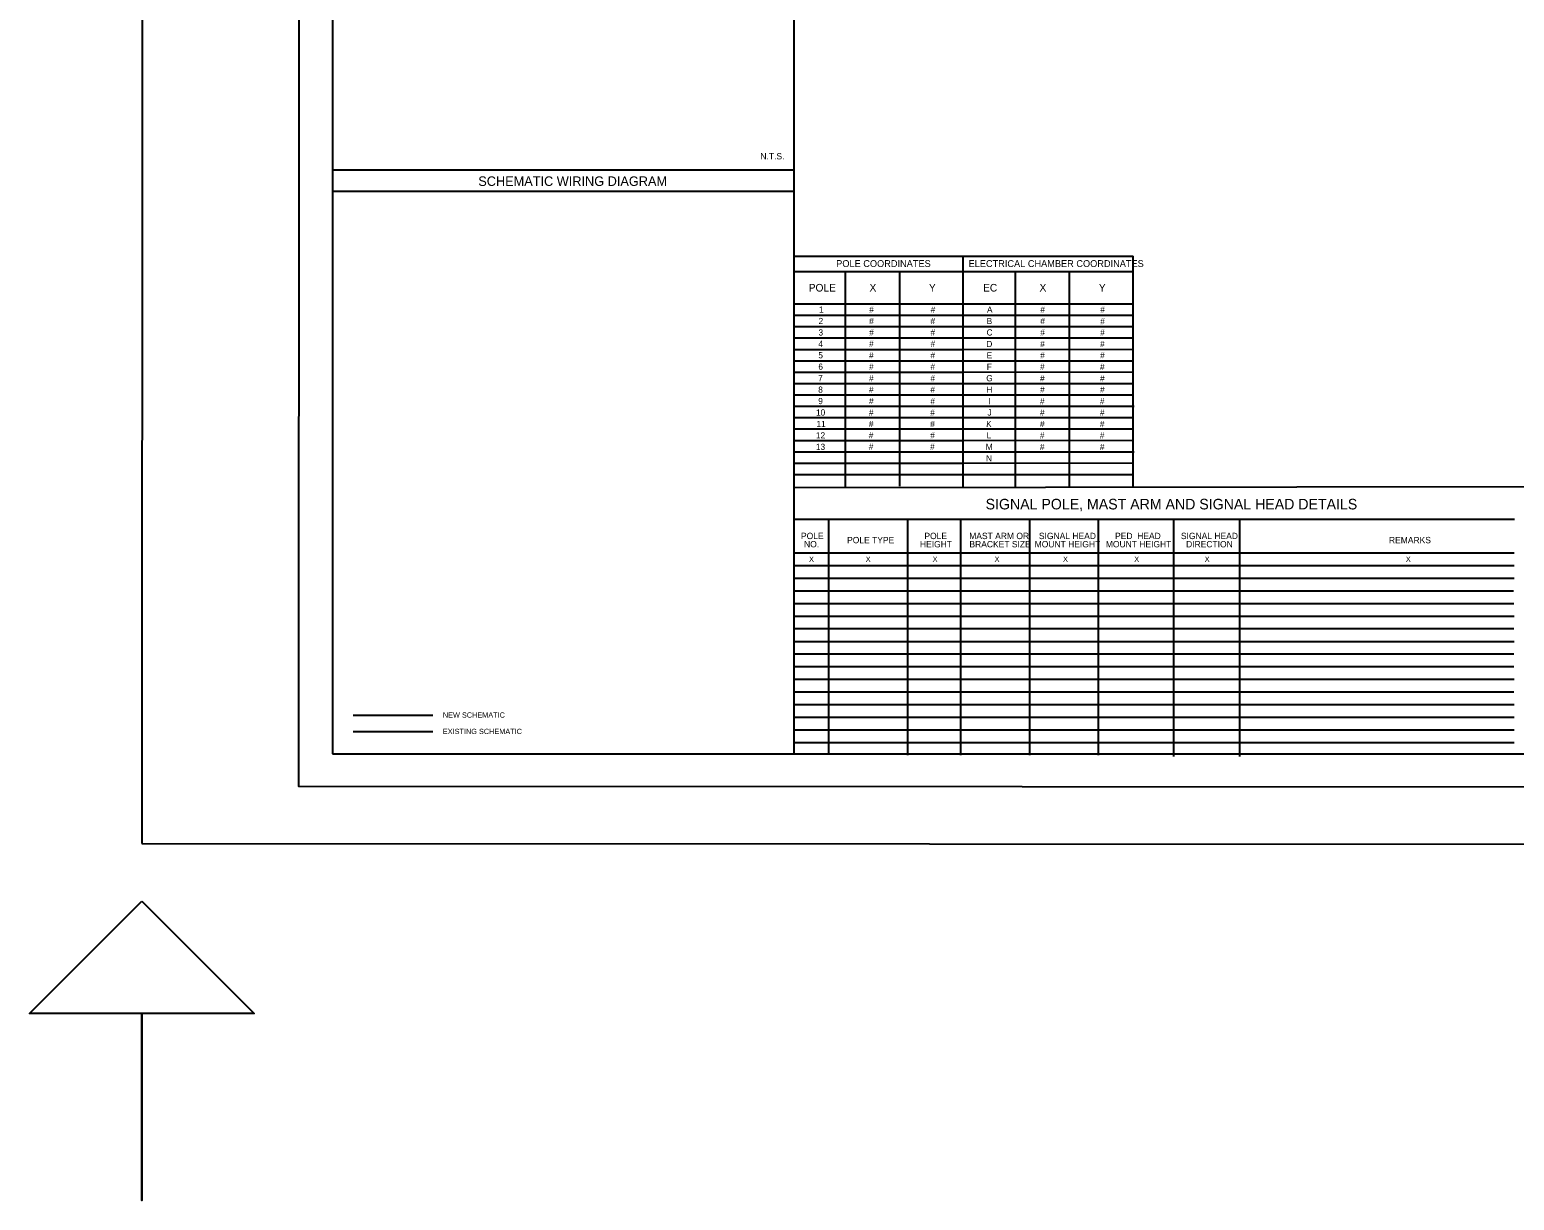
# Model space of a CAD drawing. Extents: x 595568 to 603392, y 4837996 to 4846579.
# Drawn here: x 603031.2 to 603171.6, y 4846357.1 to 4846467.9 of the extents above; entities that cross this region are included whole.
import ezdxf

# ---------------------------------------------------------------- set-up
doc = ezdxf.new("R2010")
doc.units = 0
for name, color, linetype in [('-PRINT FULLSIZE', 7, 'Continuous'), ('-PRINT HALFSIZE', 7, 'Continuous'), ('ENG_BORDER', 7, 'Continuous'), ('ENG_TITLEBLOCK', 7, 'Continuous'), ('ENG_TX_TITLEBLOCK', 7, 'Continuous'), ('ENG_WK_MISC-1', 7, 'Continuous'), ('TCS_TX_LEGEND', 7, 'Continuous'), ('TCS_WR_W', 7, 'Continuous'), ('TCS_WR_W-EXIST', 7, 'Continuous')]:
    doc.layers.add(name, color=color, linetype=linetype)

msp = doc.modelspace()

# ---------------------------------------------------------------- linework, layer by layer
at = {"layer": '-PRINT FULLSIZE'}
msp.add_lwpolyline([(603041.76, 4846390.89), (603265.21, 4846390.8), (603265.27, 4846543.39), (603041.82, 4846543.47)], close=True, dxfattribs=at)
at = {"layer": '-PRINT HALFSIZE'}
msp.add_lwpolyline([(603056.66, 4846536.38), (603261.88, 4846536.3), (603261.82, 4846396.2), (603056.6, 4846396.28)], close=True, dxfattribs=at)
at = {"layer": 'ENG_BORDER'}
msp.add_line((603103.46, 4846399.39), (603103.46, 4846533.88), dxfattribs=at)
for points in [[(603059.79, 4846533.88), (603059.79, 4846399.39)], [(603059.79, 4846399.39), (603258.62, 4846399.39), (603258.62, 4846533.88)]]:
    msp.add_lwpolyline(points, dxfattribs=at)
at = {"layer": 'ENG_TITLEBLOCK'}
for p, q in [((603059.79, 4846454.61), (603103.46, 4846454.61)), ((603059.79, 4846452.6), (603103.46, 4846452.6)), ((603103.46, 4846446.45), (603135.51, 4846446.45)), ((603119.44, 4846424.58), (603119.44, 4846446.45)), ((603135.5, 4846424.71), (603135.5, 4846446.45)), ((603103.46, 4846445.01), (603108.32, 4846445.01)), ((603108.32, 4846424.58), (603108.32, 4846445.01)), ((603108.32, 4846445.01), (603113.34, 4846445.01)), ((603113.34, 4846445.01), (603113.44, 4846445.01)), ((603113.44, 4846445.01), (603119.46, 4846445.01)), ((603113.44, 4846424.69), (603113.44, 4846444.98)), ((603119.43, 4846445.02), (603124.32, 4846445.02)), ((603124.32, 4846445.02), (603129.5, 4846445.02)), ((603124.39, 4846424.68), (603124.39, 4846445.01)), ((603129.5, 4846445.02), (603135.53, 4846445.01)), ((603129.5, 4846424.7), (603129.5, 4846445.01)), ((603103.46, 4846441.95), (603119.33, 4846441.95)), ((603119.33, 4846441.95), (603135.5, 4846441.95)), ((603103.46, 4846440.87), (603119.48, 4846440.87)), ((603103.46, 4846439.8), (603119.49, 4846439.79)), ((603119.48, 4846440.87), (603135.55, 4846440.88)), ((603119.49, 4846439.79), (603135.56, 4846439.8)), ((603103.46, 4846438.72), (603119.52, 4846438.72)), ((603119.52, 4846438.72), (603135.59, 4846438.73)), ((603103.46, 4846437.64), (603119.49, 4846437.64)), ((603119.49, 4846437.64), (603135.56, 4846437.65)), ((603103.46, 4846436.57), (603119.47, 4846436.57)), ((603103.46, 4846435.49), (603119.47, 4846435.49)), ((603119.47, 4846436.57), (603135.54, 4846436.57)), ((603119.47, 4846435.49), (603135.54, 4846435.5)), ((603103.46, 4846434.41), (603119.47, 4846434.41)), ((603119.47, 4846434.41), (603135.54, 4846434.42)), ((603103.46, 4846433.34), (603119.47, 4846433.34)), ((603119.47, 4846433.34), (603135.54, 4846433.34)), ((603103.46, 4846432.26), (603119.53, 4846432.26)), ((603119.53, 4846432.26), (603135.6, 4846432.27)), ((603103.46, 4846431.19), (603119.47, 4846431.18)), ((603103.46, 4846430.11), (603119.47, 4846430.11)), ((603119.47, 4846431.18), (603135.54, 4846431.19)), ((603119.47, 4846430.11), (603135.54, 4846430.12)), ((603103.46, 4846429.03), (603119.5, 4846429.03)), ((603119.5, 4846429.03), (603135.57, 4846429.04)), ((603103.46, 4846427.96), (603119.53, 4846427.96)), ((603119.53, 4846427.96), (603135.6, 4846427.96)), ((603103.46, 4846426.88), (603119.45, 4846426.88)), ((603103.46, 4846425.81), (603119.45, 4846425.8)), ((603119.45, 4846426.88), (603135.51, 4846426.89)), ((603119.45, 4846425.8), (603135.51, 4846425.81)), ((603103.46, 4846424.58), (603218.92, 4846424.7)), ((603103.46, 4846421.58), (603171.57, 4846421.58)), ((603106.72, 4846418.4), (603106.72, 4846421.58)), ((603114.2, 4846399.26), (603114.2, 4846421.58)), ((603114.2, 4846399.39), (603114.2, 4846421.58)), ((603119.21, 4846421.56), (603119.21, 4846421.58)), ((603119.21, 4846399.26), (603119.21, 4846421.56)), ((603125.73, 4846421.53), (603125.73, 4846421.58)), ((603125.73, 4846399.26), (603125.73, 4846421.53)), ((603132.25, 4846399.26), (603132.25, 4846421.58)), ((603139.36, 4846399.12), (603139.36, 4846421.44)), ((603145.5, 4846421.58), (603145.67, 4846421.58)), ((603145.59, 4846399.12), (603145.59, 4846421.44)), ((603103.46, 4846418.39), (603171.54, 4846418.39)), ((603103.46, 4846417.2), (603106.67, 4846417.2)), ((603106.67, 4846417.2), (603106.72, 4846417.2)), ((603106.72, 4846418.39), (603106.72, 4846418.4)), ((603106.72, 4846417.2), (603106.72, 4846418.39)), ((603106.72, 4846417.2), (603106.75, 4846417.2)), ((603106.72, 4846399.39), (603106.72, 4846417.2)), ((603106.75, 4846417.2), (603171.54, 4846417.2)), ((603106.75, 4846417.2), (603106.77, 4846417.2)), ((603103.46, 4846416), (603171.54, 4846416)), ((603103.46, 4846414.8), (603171.49, 4846414.8)), ((603103.46, 4846413.61), (603171.51, 4846413.61)), ((603103.46, 4846412.41), (603171.54, 4846412.41)), ((603103.46, 4846411.22), (603171.51, 4846411.22)), ((603103.46, 4846410.02), (603171.56, 4846410.02)), ((603103.46, 4846408.83), (603171.51, 4846408.83)), ((603103.46, 4846407.63), (603171.51, 4846407.63)), ((603103.46, 4846406.43), (603171.54, 4846406.43)), ((603103.46, 4846405.24), (603171.51, 4846405.24)), ((603103.46, 4846404.04), (603171.54, 4846404.04)), ((603103.46, 4846402.85), (603171.54, 4846402.85)), ((603103.46, 4846401.65), (603171.54, 4846401.65)), ((603103.46, 4846400.46), (603171.54, 4846400.46))]:
    msp.add_line(p, q, dxfattribs=at)
at = {"layer": 'ENG_WK_MISC-1'}
msp.add_lwpolyline([(603041.76, 4846385.43), (603052.37, 4846374.82), (603041.76, 4846374.82), (603041.76, 4846357.14), (603041.76, 4846374.82), (603031.15, 4846374.82)], close=True, dxfattribs=at)
at = {"layer": 'TCS_WR_W'}
msp.add_line((603061.76, 4846403.05), (603069.28, 4846403.05), dxfattribs=at)
at = {"layer": 'TCS_WR_W-EXIST'}
msp.add_line((603061.76, 4846401.5), (603069.28, 4846401.5), dxfattribs=at)

# ---------------------------------------------------------------- texts
at = {"layer": 'ENG_TX_TITLEBLOCK'}
for s, height, rotation, p in [('N.T.S.', 0.6, 0.0001, (603100.26, 4846455.61)), ('SCHEMATIC WIRING DIAGRAM', 0.9, 0.0001, (603073.58, 4846453.1)), ('POLE COORDINATES', 0.65, 359.9951, (603107.43, 4846445.43)), ('ELECTRICAL CHAMBER COORDINATES', 0.65, 359.9951, (603119.95, 4846445.43)), ('POLE', 0.72, 359.9951, (603104.83, 4846443.11)), ('EC', 0.72, 359.9951, (603121.32, 4846443.11)), ('X', 0.72, 359.9951, (603110.58, 4846443.11)), ('Y', 0.72, 359.9951, (603116.2, 4846443.11)), ('X', 0.72, 359.9951, (603126.66, 4846443.11)), ('Y', 0.72, 359.9951, (603132.27, 4846443.11)), ('1', 0.585, 359.8051, (603105.8, 4846441.12)), ('#', 0.585, 359.8051, (603110.55, 4846441.11)), ('#', 0.585, 359.8051, (603116.36, 4846441.11)), ('A', 0.585, 359.8051, (603121.69, 4846441.11)), ('#', 0.585, 359.8051, (603126.73, 4846441.11)), ('#', 0.585, 359.8051, (603132.4, 4846441.11)), ('2', 0.585, 359.8051, (603105.76, 4846440.03)), ('#', 0.585, 359.8051, (603110.55, 4846440.03)), ('#', 0.585, 359.8051, (603116.35, 4846440.03)), ('B', 0.585, 359.8051, (603121.66, 4846440.03)), ('#', 0.585, 359.8051, (603126.73, 4846440.03)), ('#', 0.585, 359.8051, (603132.4, 4846440.02)), ('4', 0.585, 359.8051, (603105.74, 4846437.87)), ('3', 0.585, 359.8051, (603105.75, 4846438.95)), ('#', 0.585, 359.8051, (603110.55, 4846438.95)), ('#', 0.585, 359.8051, (603110.54, 4846437.87)), ('#', 0.585, 359.8051, (603116.35, 4846438.95)), ('#', 0.585, 359.8051, (603116.35, 4846437.87)), ('C', 0.585, 359.8051, (603121.65, 4846438.95)), ('D', 0.585, 359.8051, (603121.63, 4846437.86)), ('#', 0.585, 359.8051, (603126.72, 4846438.94)), ('#', 0.585, 359.8051, (603126.72, 4846437.86)), ('#', 0.585, 359.8051, (603132.39, 4846437.86)), ('#', 0.585, 359.8051, (603132.39, 4846438.94)), ('5', 0.585, 359.8051, (603105.74, 4846436.79)), ('#', 0.585, 359.8051, (603110.54, 4846436.79)), ('#', 0.585, 359.8051, (603116.34, 4846436.78)), ('E', 0.585, 359.8051, (603121.66, 4846436.78)), ('#', 0.585, 359.8051, (603126.72, 4846436.78)), ('#', 0.585, 359.8051, (603132.39, 4846436.78)), ('6', 0.585, 359.8051, (603105.74, 4846435.71)), ('#', 0.585, 359.8051, (603110.54, 4846435.7)), ('#', 0.585, 359.8051, (603116.34, 4846435.7)), ('F', 0.585, 359.8051, (603121.67, 4846435.7)), ('#', 0.585, 359.8051, (603126.71, 4846435.7)), ('#', 0.585, 359.8051, (603132.38, 4846435.69)), ('8', 0.585, 359.8051, (603105.73, 4846433.54)), ('7', 0.585, 359.8051, (603105.72, 4846434.62)), ('#', 0.585, 359.8051, (603110.53, 4846433.54)), ('#', 0.585, 359.8051, (603110.53, 4846434.62)), ('#', 0.585, 359.8051, (603116.33, 4846433.54)), ('#', 0.585, 359.8051, (603116.33, 4846434.62)), ('G', 0.585, 359.8051, (603121.62, 4846434.62)), ('H', 0.585, 359.8051, (603121.63, 4846433.53)), ('#', 0.585, 359.8051, (603126.71, 4846434.61)), ('#', 0.585, 359.8051, (603126.71, 4846433.53)), ('#', 0.585, 359.8051, (603132.38, 4846434.61)), ('#', 0.585, 359.8051, (603132.38, 4846433.53)), ('9', 0.585, 359.8051, (603105.73, 4846432.46)), ('#', 0.585, 359.8051, (603110.53, 4846432.46)), ('#', 0.585, 359.8051, (603116.33, 4846432.45)), ('I', 0.585, 359.8051, (603121.8, 4846432.45)), ('#', 0.585, 359.8051, (603126.7, 4846432.45)), ('#', 0.585, 359.8051, (603132.37, 4846432.45)), ('10', 0.585, 359.8051, (603105.52, 4846431.38)), ('#', 0.585, 359.8051, (603110.52, 4846431.37)), ('#', 0.585, 359.8051, (603116.32, 4846431.37)), ('J', 0.585, 359.8051, (603121.73, 4846431.37)), ('#', 0.585, 359.8051, (603126.7, 4846431.37)), ('#', 0.585, 359.8051, (603132.37, 4846431.37)), ('12', 0.585, 359.8051, (603105.51, 4846429.21)), ('11', 0.585, 359.8051, (603105.56, 4846430.29)), ('#', 0.585, 359.8051, (603110.52, 4846430.29)), ('#', 0.585, 359.8051, (603116.32, 4846430.29)), ('K', 0.585, 359.8051, (603121.61, 4846430.29)), ('#', 0.585, 359.8051, (603126.7, 4846430.29)), ('#', 0.585, 359.8051, (603132.36, 4846430.28)), ('13', 0.585, 359.8051, (603105.51, 4846428.13)), ('#', 0.585, 359.8051, (603110.51, 4846428.13)), ('#', 0.585, 359.8051, (603110.51, 4846429.21)), ('#', 0.585, 359.8051, (603116.32, 4846429.21)), ('#', 0.585, 359.8051, (603116.31, 4846428.13)), ('M', 0.585, 359.8051, (603121.57, 4846428.12)), ('L', 0.585, 359.8051, (603121.65, 4846429.21)), ('#', 0.585, 359.8051, (603126.69, 4846428.12)), ('#', 0.585, 359.8051, (603126.69, 4846429.2)), ('#', 0.585, 359.8051, (603132.36, 4846429.2)), ('#', 0.585, 359.8051, (603132.36, 4846428.12)), ('N', 0.585, 359.8051, (603121.6, 4846427.04)), ('SIGNAL POLE, MAST ARM AND SIGNAL HEAD DETAILS', 1, 0.0001, (603121.56, 4846422.5)), ('POLE', 0.6, 0.0001, (603104.1, 4846419.69)), ('POLE', 0.6, 0.0001, (603115.77, 4846419.69)), ('MAST ARM OR', 0.6, 0.0001, (603120.01, 4846419.69)), ('SIGNAL HEAD', 0.6, 0.0001, (603126.6, 4846419.69)), ('PED  HEAD', 0.6, 0.0001, (603133.8, 4846419.69)), ('SIGNAL HEAD', 0.6, 0.0001, (603140.03, 4846419.69)), ('NO.', 0.6, 0.0001, (603104.39, 4846418.91)), ('POLE TYPE', 0.6, 0.0001, (603108.46, 4846419.3)), ('HEIGHT', 0.6, 0.0001, (603115.35, 4846418.91)), ('BRACKET SIZE', 0.6, 0.0001, (603120.03, 4846418.91)), ('MOUNT HEIGHT', 0.6, 0.0001, (603126.2, 4846418.91)), ('MOUNT HEIGHT', 0.6, 0.0001, (603132.93, 4846418.91)), ('DIRECTION', 0.6, 0.0001, (603140.52, 4846418.91)), ('REMARKS', 0.6, 0.0001, (603159.71, 4846419.3)), ('X', 0.501, 0.0001, (603104.86, 4846417.54)), ('X', 0.501, 0.0001, (603110.22, 4846417.54)), ('X', 0.501, 0.0001, (603116.55, 4846417.54)), ('X', 0.501, 0.0001, (603122.41, 4846417.54)), ('X', 0.501, 0.0001, (603128.88, 4846417.54)), ('X', 0.501, 0.0001, (603135.62, 4846417.54)), ('X', 0.501, 0.0001, (603142.28, 4846417.54)), ('X', 0.501, 0.0001, (603161.3, 4846417.54))]:
    msp.add_text(s, height=height, rotation=rotation, dxfattribs=at).set_placement(p)
at = {"layer": 'TCS_TX_LEGEND'}
for s, p in [('NEW SCHEMATIC', (603070.23, 4846402.8)), ('EXISTING SCHEMATIC', (603070.23, 4846401.25))]:
    msp.add_text(s, height=0.5, rotation=359.9774, dxfattribs=at).set_placement(p)

doc.saveas('drawing.dxf')
